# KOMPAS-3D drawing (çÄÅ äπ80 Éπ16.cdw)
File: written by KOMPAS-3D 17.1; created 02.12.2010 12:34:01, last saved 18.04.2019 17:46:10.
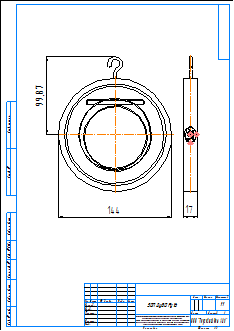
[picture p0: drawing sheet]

Sheet 1: A3, portrait

Title block, sheet 1: name: ЗОП Ду80 Ру16; material: Внимание! Данный продукт является объектом авторского права ООО «Торговый Дом АДЛ». / Запрещается изменение, копирование, распространение / (в том числе путем копирования на другие сайты и ресурсы в Интернете) / или любое иное использование информации и объектов без предварительного / согласия правообладателя (ООО «Торговый Дом АДЛ»).; scale: 1:1; sheets: 1; organisation: ООО "Торговый дом АДЛ"; sheet format: A3; stored path: \\adlc.lan\data\АДЛ_ПКД\3D-модели\ADL production\Клапаны обратные ГРАНЛОК\ЗОП\KOMPAS 2D\ЗОП Ду80 Ру16.cdw

Views: Спереди 1, Проекционный вид 2
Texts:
  bsv
  adl
Dimensions and other numbers on the sheet: 144; 17; 99,87; 1:1; 1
